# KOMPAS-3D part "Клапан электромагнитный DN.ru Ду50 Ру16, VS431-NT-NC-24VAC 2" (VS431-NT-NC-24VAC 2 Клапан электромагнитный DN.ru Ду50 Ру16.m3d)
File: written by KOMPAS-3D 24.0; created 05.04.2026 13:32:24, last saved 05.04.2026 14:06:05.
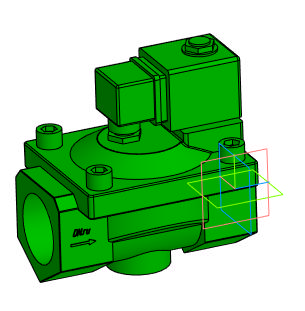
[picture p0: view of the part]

Document properties: Автор: artio; Полное имя файла: C:\Users\artio\OneDrive\Рабочий стол\Клапан электромагнитный DN.ru\VS431\VS431-NT-NC\VS431-NT-NC-24VAC\Ду50\VS431-NT-NC-24VAC 2 Клапан электромагнитный DN.ru Ду50 Ру16.m3d

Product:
- Body: Тело 1  | qty 1
    Масса: 6.703651
- Part/product: Клапан электромагнитный DN.ru Ду50 Ру16  | designation VS431-NT-NC-24VAC 2
    Масса: 3.341
    Раздел спецификации: Прочие изделия
    Примечание: D130-05512
    additional columns: ef56311e-7521-43dc-8291-0e6108b3d81d; artio; c; Шероховатость не задана; Да

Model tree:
1. Операция без истории:1

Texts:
  VS431-NT-NC-24VAC 2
